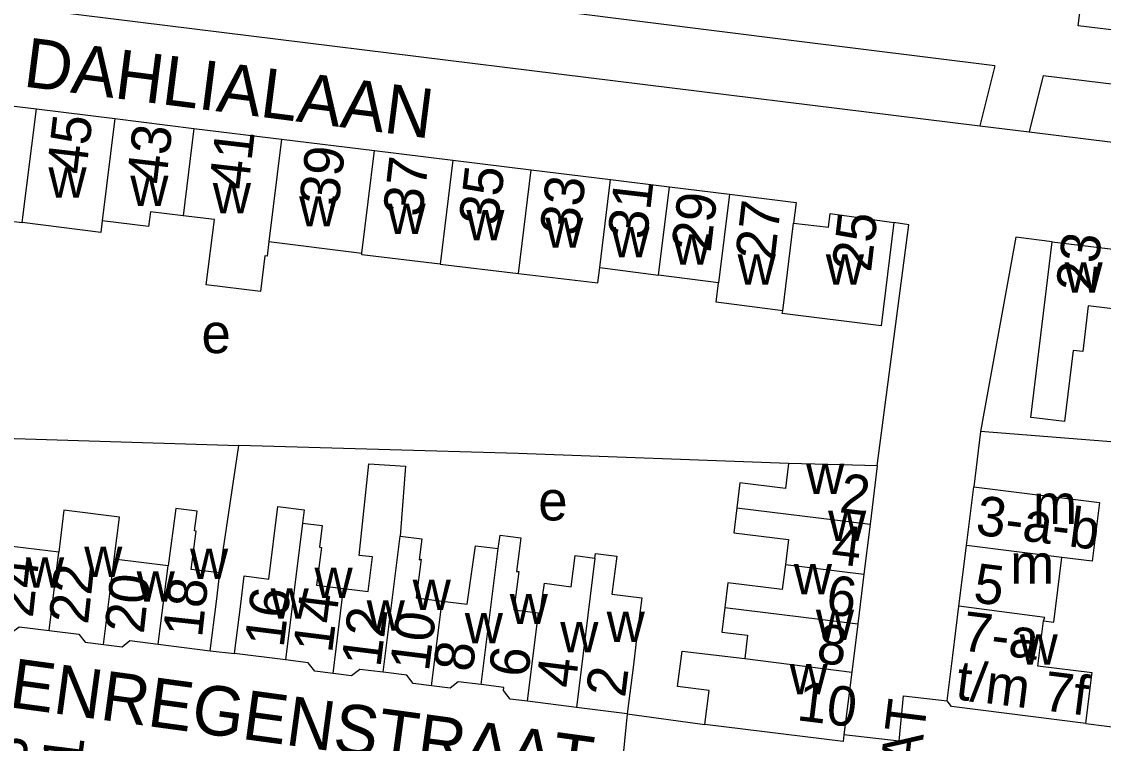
# Model space of a CAD drawing. Extents: x 161258 to 163262, y 380749 to 382054.
# Drawn here: x 162035.8 to 162145.4, y 381397.6 to 381470.7 of the extents above; entities that cross this region are included whole.
import ezdxf

# ---------------------------------------------------------------- set-up
doc = ezdxf.new("R2010")
doc.units = 0
for name, color, linetype in [('BLT_Basislijn', 7, 'Continuous'), ('BLT_Bebouwing', 7, 'Continuous'), ('BLT_Centroide', 7, 'Continuous'), ('BLT_Huisnummer', 7, 'Continuous'), ('BLT_Huisnummer_ tussenligend', 7, 'Continuous'), ('BLT_Huisnummer_reeks', 7, 'Continuous'), ('BLT_Onderverdeling_panden', 7, 'Continuous'), ('BLT_Straatnaam', 7, 'Continuous'), ('BLT_Straatnaam_verkleind', 7, 'Continuous'), ('BLT_Vlakafsluiter', 7, 'Continuous')]:
    doc.layers.add(name, color=color, linetype=linetype)

msp = doc.modelspace()

# ---------------------------------------------------------------- linework, layer by layer
at = {"layer": 'BLT_Basislijn'}
for p, q in [((161998.38, 381476.79), (162132.88, 381460.18)), ((162139.31, 381465.27), (162254.2, 381451.16)), ((162132.95, 381429.2), (162132.29, 381423.61)), ((162191.84, 381424.6), (162132.95, 381429.2)), ((162055.91, 381414.88), (162057.83, 381427.78)), ((162086.14, 381426.97), (162057.83, 381427.78)), ((162113.52, 381425.96), (162086.14, 381426.97)), ((162054.94, 381407), (162057.39, 381406.71)), ((162125.17, 381402.42), (162129.57, 381401.92)), ((162097.18, 381400.62), (162105.05, 381399.54)), ((162143.62, 381399.63), (162148.58, 381399.01)), ((162124.73, 381397.84), (162119.13, 381398.47))]:
    msp.add_line(p, q, dxfattribs=at)
for points in [[(162114.06, 381468.8), (161999.17, 381483.24)], [(162134.4, 381466.25), (162114.06, 381468.8)], [(162134.4, 381466.25), (162132.88, 381460.18)], [(162139.31, 381465.27), (162137.88, 381459.56)], [(162132.88, 381460.18), (162137.88, 381459.56)], [(162137.88, 381459.56), (162248.35, 381445.94), (162250.95, 381446.22), (162252.67, 381447.37), (162253.65, 381449.05), (162254.2, 381451.16)], [(162122.5, 381425.72), (162125.71, 381450.14), (162124.19, 381450.39)], [(162140.22, 381448.44), (162136.52, 381448.9), (162132.95, 381429.2)], [(162007.94, 381434.88), (162007.99, 381429.33), (162057.83, 381427.78)]]:
    msp.add_lwpolyline(points, dxfattribs=at)
at = {"layer": 'BLT_Bebouwing'}
for p, q in [((162142.86, 381470.31), (162144.15, 381480.8)), ((162149.32, 381469.53), (162142.86, 381470.31)), ((162030.77, 381462.7), (162037.33, 381461.89)), ((162037.33, 381461.89), (162045.27, 381460.91)), ((162045.27, 381460.91), (162053.29, 381459.92)), ((162053.29, 381459.92), (162062.16, 381458.83)), ((162062.16, 381458.83), (162071.58, 381457.67)), ((162071.58, 381457.67), (162079.52, 381456.69)), ((162079.52, 381456.69), (162087.46, 381455.72)), ((162087.46, 381455.72), (162095.49, 381454.73)), ((162095.49, 381454.73), (162101.45, 381453.99)), ((162101.45, 381453.99), (162107.52, 381453.24)), ((162029.36, 381451.19), (162035.9, 381450.37)), ((162060.88, 381448.45), (162070.3, 381447.28)), ((162078.22, 381446.16), (162086.17, 381445.23)), ((162094.4, 381445.82), (162100.35, 381445.04)), ((162106.41, 381444.26), (162100.35, 381445.04)), ((162122.5, 381425.72), (162121.77, 381419.82)), ((162131.55, 381417.67), (162132.29, 381423.61)), ((162121.77, 381419.82), (162121.14, 381414.75)), ((162039.59, 381416.98), (162034.02, 381417.67)), ((162130.77, 381411.52), (162131.55, 381417.67)), ((162050.69, 381415.6), (162045.21, 381416.28)), ((162121.14, 381414.75), (162120.52, 381409.72)), ((162130.15, 381406.53), (162130.77, 381411.52)), ((162120.52, 381409.72), (162119.92, 381404.82)), ((162138.77, 381405.45), (162139.34, 381410.02)), ((162049.65, 381407.66), (162054.94, 381407)), ((162062.55, 381406.06), (162057.39, 381406.71)), ((162129.57, 381401.92), (162130.15, 381406.53)), ((162119.92, 381404.82), (162119.13, 381398.47)), ((162092.02, 381401.26), (162087.06, 381401.88)), ((162097.18, 381400.62), (162092.02, 381401.26))]:
    msp.add_line(p, q, dxfattribs=at)
for points in [[(162107.52, 381453.24), (162114.27, 381452.41), (162114.01, 381450.33)], [(162052.2, 381451.05), (162048.88, 381451.45), (162048.69, 381449.97), (162043.99, 381450.55)], [(162060.88, 381448.45), (162060.69, 381446.99), (162060.48, 381447.01), (162060.03, 381443.38), (162054.52, 381444.06), (162055.37, 381450.68), (162052.2, 381451.05)], [(162114.01, 381450.33), (162117.55, 381449.9), (162117.74, 381451.29), (162124.19, 381450.39)], [(162043.99, 381450.55), (162043.84, 381449.37), (162035.9, 381450.37)], [(162124.19, 381450.39), (162122.9, 381439.92), (162112.88, 381441.15), (162112.92, 381441.44)], [(162149.38, 381441.27), (162143.87, 381441.94), (162143.32, 381437.31), (162142.33, 381437.43), (162141.46, 381430.23), (162138.67, 381430.57), (162138.04, 381430.64), (162140.22, 381448.44)], [(162140.22, 381448.44), (162146.67, 381447.65), (162146.5, 381446.27), (162149.94, 381445.85)], [(162078.22, 381446.16), (162070.28, 381447.1), (162070.3, 381447.28)], [(162086.17, 381445.23), (162094.21, 381444.28), (162094.4, 381445.82)], [(162112.92, 381441.44), (162106.18, 381442.31), (162106.41, 381444.26)], [(162068.45, 381413.3), (162070.95, 381412.99), (162071.38, 381416.5), (162070.03, 381416.65), (162071.01, 381425.93), (162074.73, 381425.71), (162074.18, 381418.62)], [(162113.52, 381425.96), (162113.2, 381423.45), (162108.59, 381424.02), (162108.27, 381421.49)], [(162122.5, 381425.72), (162117.5, 381425.87), (162113.52, 381425.96)], [(162132.29, 381423.61), (162145.02, 381422.01), (162144.28, 381416.07), (162141.21, 381416.45)], [(162055.91, 381414.88), (162053.02, 381415.23), (162053.51, 381419.12), (162053.35, 381419.14), (162053.6, 381421.13), (162051.45, 381421.41), (162050.69, 381415.6)], [(162057.39, 381406.71), (162058.02, 381411.71), (162058.38, 381414.57), (162060.86, 381414.26), (162061.77, 381421.61), (162064.44, 381421.28), (162064.27, 381419.91)], [(162108.27, 381421.49), (162107.96, 381418.95), (162113.5, 381418.26), (162113.19, 381415.73)], [(162045.21, 381416.28), (162045.74, 381420.53), (162040.12, 381421.23), (162039.59, 381416.98)], [(162064.27, 381419.91), (162066.27, 381419.67), (162065.99, 381417.49), (162066.19, 381417.46), (162065.71, 381413.65), (162068.45, 381413.3)], [(162074.18, 381418.62), (162076.37, 381418.35), (162076.1, 381416.21), (162076.29, 381416.29), (162075.8, 381412.35), (162078.43, 381412.03)], [(162084.09, 381417.36), (162084.29, 381418.7), (162086.39, 381418.44), (162086.23, 381417.1), (162085.97, 381415.03), (162086.18, 381415.01), (162085.7, 381411.14), (162088.17, 381410.83)], [(162078.43, 381412.03), (162080.96, 381411.71), (162081.82, 381417.64), (162084.09, 381417.36)], [(162088.17, 381410.83), (162088.37, 381410.81), (162088.58, 381412.46), (162088.79, 381413.83), (162091.5, 381413.47), (162091.9, 381416.64), (162093.9, 381416.39)], [(162093.9, 381416.39), (162093.96, 381416.86), (162096.11, 381416.59), (162095.63, 381412.72), (162098.64, 381412.35), (162098.16, 381408.5), (162097.8, 381405.58), (162097.18, 381400.62)], [(162139.34, 381410.02), (162140.39, 381409.89), (162141.21, 381416.45)], [(162054.94, 381407), (162055.56, 381411.98), (162055.91, 381414.88)], [(162113.19, 381415.73), (162112.88, 381413.2), (162107.36, 381413.88), (162107.05, 381411.38)], [(162107.05, 381411.38), (162106.74, 381408.88), (162109.36, 381408.56), (162109.07, 381406.22)], [(162032.95, 381409.06), (162034.8, 381408.83), (162035.58, 381409.43), (162038.61, 381409.06)], [(162038.61, 381409.06), (162041.63, 381408.68), (162042.27, 381407.87), (162044.14, 381407.63)], [(162044.14, 381407.63), (162046.01, 381407.4), (162046.8, 381408.02), (162049.65, 381407.66)], [(162067.38, 381404.69), (162065.52, 381404.92), (162064.85, 381405.78), (162062.55, 381406.06)], [(162105.05, 381399.54), (162105.48, 381402.98), (162102.28, 381403.37), (162102.73, 381406.97), (162109.07, 381406.22)], [(162072.46, 381404.81), (162070.08, 381405.11), (162069.24, 381404.46), (162067.38, 381404.69)], [(162143.62, 381399.63), (162144.24, 381404.59), (162144.26, 381404.76), (162138.77, 381405.45)], [(162077.36, 381403.44), (162075.49, 381403.67), (162074.84, 381404.52), (162072.46, 381404.81)], [(162082.37, 381403.56), (162080.05, 381403.85), (162079.23, 381403.21), (162077.36, 381403.44)], [(162087.06, 381401.88), (162085.33, 381402.1), (162084.65, 381402.97), (162084.68, 381403.27), (162082.37, 381403.56)], [(162143.62, 381399.63), (162130.02, 381401.34), (162129.57, 381401.92)], [(162119.13, 381398.47), (162119.05, 381397.81), (162105.05, 381399.54)]]:
    msp.add_lwpolyline(points, dxfattribs=at)
at = {"layer": 'BLT_Onderverdeling_panden'}
for p, q in [((162035.9, 381450.37), (162037.33, 381461.89)), ((162045.27, 381460.91), (162043.99, 381450.55)), ((162053.29, 381459.92), (162052.2, 381451.05)), ((162062.16, 381458.83), (162060.88, 381448.45)), ((162070.3, 381447.28), (162071.58, 381457.67)), ((162079.52, 381456.69), (162078.22, 381446.16)), ((162086.17, 381445.23), (162087.46, 381455.72)), ((162094.4, 381445.82), (162095.49, 381454.73)), ((162100.35, 381445.04), (162101.45, 381453.99)), ((162107.52, 381453.24), (162106.41, 381444.26)), ((162112.92, 381441.44), (162114.01, 381450.33)), ((162108.27, 381421.49), (162121.77, 381419.82)), ((162064.27, 381419.91), (162062.55, 381406.06)), ((162072.46, 381404.81), (162074.18, 381418.62)), ((162038.61, 381409.06), (162039.59, 381416.98)), ((162082.37, 381403.56), (162084.09, 381417.36)), ((162141.21, 381416.45), (162131.55, 381417.67)), ((162044.14, 381407.63), (162045.21, 381416.28)), ((162093.9, 381416.39), (162092.02, 381401.26)), ((162049.65, 381407.66), (162050.69, 381415.6)), ((162113.19, 381415.73), (162121.14, 381414.75)), ((162067.38, 381404.69), (162068.45, 381413.3)), ((162077.36, 381403.44), (162078.43, 381412.03)), ((162087.06, 381401.88), (162088.17, 381410.83)), ((162107.05, 381411.38), (162120.52, 381409.72)), ((162109.07, 381406.22), (162119.92, 381404.82))]:
    msp.add_line(p, q, dxfattribs=at)
msp.add_lwpolyline([(162139.34, 381410.02), (162139.47, 381410.38), (162130.77, 381411.52)], dxfattribs=at)
at = {"layer": 'BLT_Vlakafsluiter'}
for p, q in [((162124.73, 381397.84), (162125.17, 381402.42)), ((162097.18, 381400.62), (162096.16, 381390.7))]:
    msp.add_line(p, q, dxfattribs=at)

# ---------------------------------------------------------------- texts
at = {"layer": 'BLT_Centroide'}
for s, p in [('w', (162038.55, 381452.9)), ('w', (162046.84, 381452.07)), ('w', (162055.2, 381451.31)), ('w', (162063.94, 381449.98)), ('w', (162072.89, 381449.22)), ('w', (162080.87, 381448.59)), ('w', (162088.86, 381447.82)), ('w', (162095.57, 381446.87)), ('w', (162101.78, 381446.11)), ('w', (162108.36, 381444.08)), ('w', (162117.29, 381444.08)), ('w', (162141.47, 381443.28)), ('e', (162054.05, 381437.15)), ('w', (162115.29, 381422.88)), ('e', (162088.16, 381420.2)), ('m', (162138.28, 381419.84)), ('w', (162117.52, 381418.12)), ('w', (162042.17, 381414.48)), ('w', (162052.89, 381414.28)), ('w', (162036.27, 381413.38)), ('m', (162135.97, 381413.78)), ('w', (162047.48, 381411.97)), ('w', (162065.5, 381412.34)), ('w', (162114.05, 381412.72)), ('w', (162075.44, 381411.11)), ('w', (162061.05, 381410.25)), ('w', (162085.27, 381409.69)), ('w', (162070.78, 381409.02)), ('w', (162080.72, 381407.75)), ('w', (162095.09, 381407.89)), ('w', (162116.28, 381408.09)), ('w', (162090.39, 381406.84)), ('w', (162136.92, 381405.59)), ('w', (162113.62, 381402.59))]:
    msp.add_text(s, height=4, dxfattribs=at).set_placement(p)
at = {"layer": 'BLT_Huisnummer'}
for s, rotation, p in [('45', 83.3803, (162042.34, 381455.15)), ('41', 83.3803, (162058.77, 381453.6)), ('37', 83.3803, (162076.39, 381450.87)), ('33', 83.3803, (162092.28, 381448.95)), ('29', 83.3803, (162105.62, 381447.29)), ('25', 83.3803, (162121.86, 381445.28)), ('23', 83.0053, (162144.54, 381443.19)), ('2', 352.9544, (162118.56, 381421.04)), ('22', 83.8144, (162042.55, 381409.59)), ('18', 83.8169, (162054.1, 381408.25)), ('6', 352.9593, (162117.19, 381410.72)), ('16', 82.8995, (162062.36, 381407.23)), ('10', 82.9054, (162077.08, 381404.81)), ('6', 82.9037, (162087.1, 381404.19)), ('2', 82.9119, (162096.95, 381402.17)), ('10', 352.9565, (162114.26, 381399.97)), ('21', 82.8685, (162041.48, 381392.2))]:
    msp.add_text(s, height=4, rotation=rotation, dxfattribs=at).set_placement(p)
at = {"layer": 'BLT_Huisnummer_ tussenligend'}
for s, rotation, p in [('43', 83.3803, (162050.43, 381454.15)), ('39', 83.3803, (162067.92, 381451.98)), ('35', 83.3803, (162084.07, 381449.97)), ('31', 83.3803, (162099.16, 381448.59)), ('27', 83.3803, (162112.09, 381446.43)), ('4', 352.9544, (162117.72, 381415.86)), ('24', 83.8144, (162036.96, 381410.26)), ('5', 352.8251, (162132.13, 381411.92)), ('20', 83.8169, (162048.2, 381408.64)), ('14', 82.8995, (162067.27, 381406.68)), ('12', 82.9054, (162072.17, 381405.24)), ('8', 352.9593, (162116.24, 381405.8)), ('8', 82.9037, (162081.5, 381404.75)), ('4', 82.9119, (162091.9, 381403.11)), ('23', 82.8685, (162035.82, 381392.3))]:
    msp.add_text(s, height=4, rotation=rotation, dxfattribs=at).set_placement(p)
at = {"layer": 'BLT_Huisnummer_reeks'}
for s, rotation, p in [('3-a-b', 352.7816, (162132.36, 381418.78)), ('7-a', 352.8299, (162130.94, 381407.05)), ('t/m 7f', 352.8299, (162130.34, 381402.09))]:
    msp.add_text(s, height=4, rotation=rotation, dxfattribs=at).set_placement(p)
at = {"layer": 'BLT_Straatnaam'}
for s, rotation, p in [('DAHLIALAAN', 352.6951, (162035.9, 381464.18)), ('GOUDENREGENSTRAAT', 352.2398, (162014.59, 381404))]:
    msp.add_text(s, height=5, rotation=rotation, dxfattribs=at).set_placement(p)
at = {"layer": 'BLT_Straatnaam_verkleind'}
msp.add_text('SERINGENSTRAAT', height=3.9999, rotation=82.9004, dxfattribs=at).set_placement((162121.56, 381353.1))

doc.saveas('drawing.dxf')
